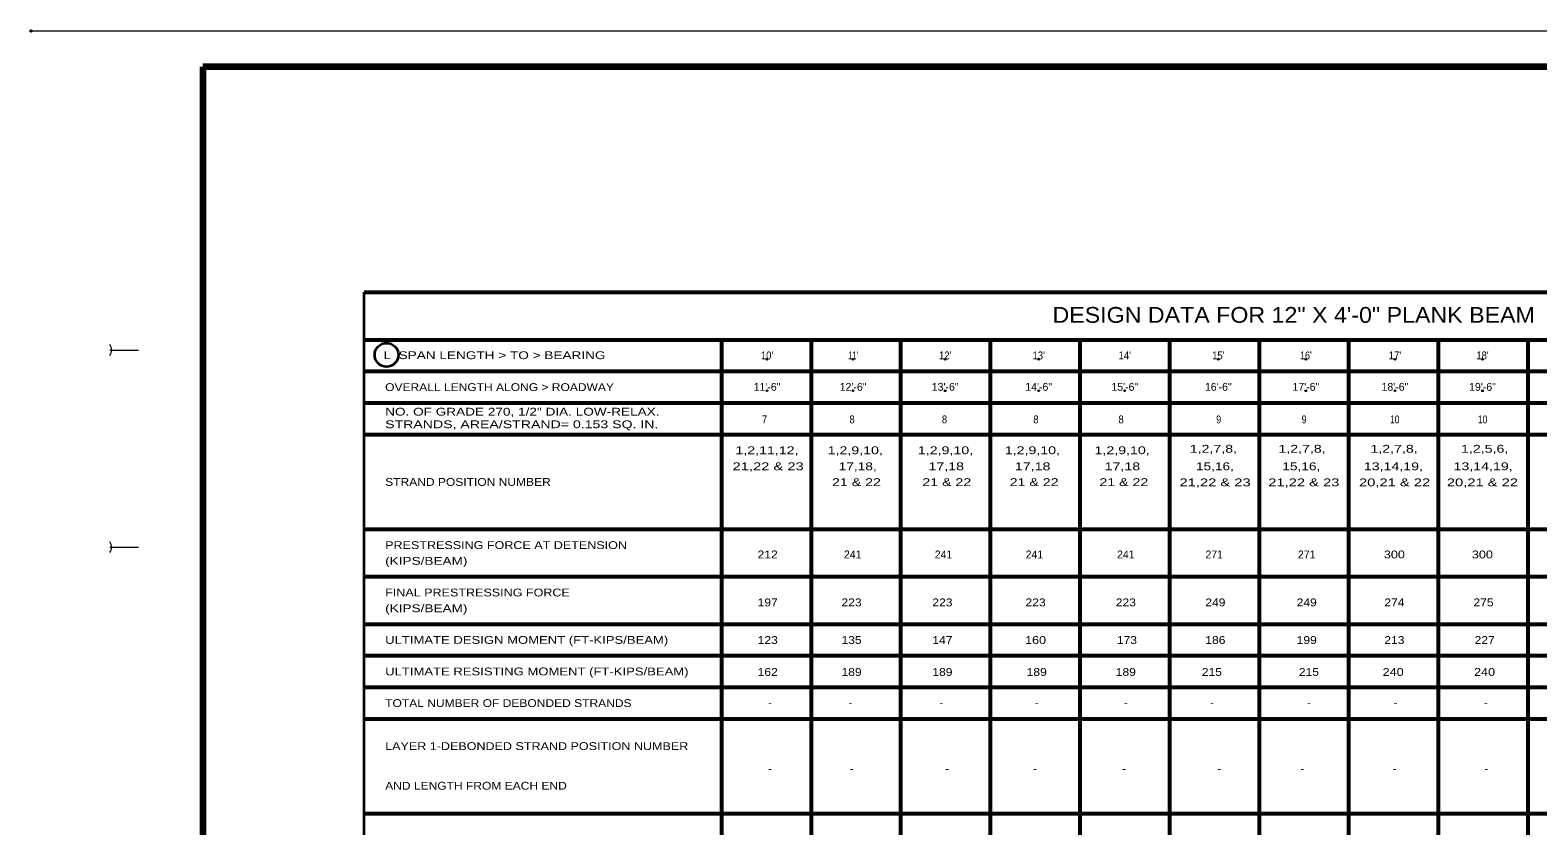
# Model space of a CAD drawing. Extents: x 758 to 1184, y 2441 to 2716.
# Drawn here: x 758.4 to 1021.3, y 2577.5 to 2716.2 of the extents above; entities that cross this region are included whole.
import ezdxf
from ezdxf.enums import TextEntityAlignment as Align

# ---------------------------------------------------------------- set-up
doc = ezdxf.new("R2010")
doc.units = 0
doc.header["$LTSCALE"] = 0.55
doc.header["$PDMODE"] = 32
doc.header["$PDSIZE"] = 0.275
for name, color, linetype, lineweight in [('1', 7, 'Continuous', 25), ('20', 7, 'Continuous', 13), ('61', 7, 'Continuous', 13), ('7', 7, 'Continuous', 53)]:
    doc.layers.add(name, color=color, linetype=linetype, lineweight=lineweight)

msp = doc.modelspace()

# ---------------------------------------------------------------- linework, layer by layer
at = {"layer": '1'}
msp.add_point((758.5283, 2716.0547), dxfattribs=at)
at = {"layer": '20'}
msp.add_lwpolyline([(879.0006, 2662.2371), (879.0006, 2662.2371), (933.7992, 2662.2371), (933.7992, 2662.2371)], close=True, dxfattribs=at)
for p in [(886.8967, 2658.8122), (901.9042, 2658.8122), (917.9579, 2658.8122), (934.2732, 2658.8122), (965.5959, 2658.8122), (980.8649, 2658.8122), (996.3955, 2658.8122), (1011.6646, 2658.8122), (886.8967, 2653.3323), (901.9042, 2653.3323), (917.9579, 2653.3323), (934.2737, 2653.3323), (949.2807, 2653.3323), (980.8649, 2653.3323), (996.3955, 2653.3323), (1011.6646, 2653.3322)]:
    msp.add_point(p, dxfattribs=at)
at = {"layer": '61'}
for p, q in [((758.5283, 2716.0547), (1183.5658, 2716.0547)), ((772.2783, 2660.4297), (777.2783, 2660.4297)), ((772.2783, 2626.0547), (777.2783, 2626.0547))]:
    msp.add_line(p, q, dxfattribs=at)
at = {"layer": '61', "lineweight": 158}
for p, q in [((788.5283, 2709.8172), (788.5283, 2447.3172)), ((1177.2783, 2709.8172), (788.5283, 2709.8172))]:
    msp.add_line(p, q, dxfattribs=at)
at = {"layer": '61'}
for centre, end in [((771.0293, 2660.4345), 36.86989), ((771.0293, 2626.0595), 36.50143)]:
    msp.add_arc(centre, 1.5625, 323.13009, end, dxfattribs=at)
at = {"layer": '7', "lineweight": 35}
for p, q in [((816.6381, 2631.3871), (816.6381, 2670.4996)), ((816.6381, 2579.6246), (816.6381, 2631.3871)), ((816.6381, 2562.5871), (816.6381, 2581.3621))]:
    msp.add_line(p, q, dxfattribs=at)
at = {"layer": '7'}
for p, q in [((816.6381, 2670.4996), (1144.6256, 2670.4996)), ((816.6381, 2662.2371), (1144.6256, 2662.2371)), ((879.0006, 2510.7871), (879.0006, 2662.2371)), ((894.6256, 2510.7871), (894.6256, 2662.2371)), ((910.2506, 2510.7871), (910.2506, 2662.2371)), ((925.8756, 2510.7871), (925.8756, 2662.2371)), ((941.5006, 2510.7871), (941.5006, 2662.2371)), ((957.1256, 2510.7871), (957.1256, 2662.2371)), ((972.7506, 2510.7871), (972.7506, 2662.2371)), ((988.3756, 2510.7871), (988.3756, 2662.2371)), ((1004.0006, 2510.7871), (1004.0006, 2662.2371)), ((1019.6256, 2510.7871), (1019.6256, 2662.2371)), ((816.6381, 2656.7246), (1144.6256, 2656.7246)), ((816.6381, 2651.2246), (1144.6256, 2651.2246)), ((816.6381, 2645.7121), (1144.6256, 2645.7121)), ((816.6381, 2629.1871), (1144.6256, 2629.1871)), ((816.6381, 2620.9371), (1144.6256, 2620.9371)), ((816.6381, 2612.6746), (1144.6256, 2612.6746)), ((816.6381, 2607.1621), (1144.6256, 2607.1621)), ((816.6381, 2601.6496), (1144.6256, 2601.6496)), ((816.6381, 2596.1496), (1144.6256, 2596.1496)), ((816.6381, 2579.6246), (1144.6256, 2579.6246))]:
    msp.add_line(p, q, dxfattribs=at)
at = {"layer": '7', "lineweight": 35}
msp.add_circle((820.5437, 2659.5955), 2.0652, dxfattribs=at)

# ---------------------------------------------------------------- texts
at = {"layer": '20'}
for s, width, p in [("10'", 0.9, (886.8968, 2658.8122)), ("11'", 0.65, (901.9043, 2658.8122)), ("12'", 0.9, (917.958, 2658.8122)), ("13'", 0.9, (934.2733, 2658.8122)), ("14'", 0.9, (949.2807, 2658.8122)), ("15'", 0.9, (965.596, 2658.8122)), ("16'", 0.85, (980.865, 2658.8122)), ("17'", 0.9, (996.3956, 2658.8122)), ("18'", 0.9, (1011.6648, 2658.8122)), ('7', 0.9, (886.45, 2647.6553)), ('8', 0.9, (901.7315, 2647.6553)), ('8', 0.9, (917.8443, 2647.6553)), ('8', 0.9, (933.7885, 2647.6553)), ('8', 0.9, (948.6401, 2647.6553)), ('9', 0.85, (965.6592, 2647.6553)), ('9', 0.85, (980.5574, 2647.6553)), ('10', 0.8, (996.3618, 2647.6553)), ('10', 0.8, (1011.69, 2647.6553)), ('1,2,11,12,', 1.35, (886.8799, 2642.2767)), ('1,2,9,10,', 1.35, (902.2795, 2642.2767)), ('1,2,9,10,', 1.35, (918.0243, 2642.2767)), ('1,2,9,10,', 1.35, (933.1757, 2642.2767)), ('1,2,9,10,', 1.35, (948.8212, 2642.2767)), ('1,2,7,8,', 1.35, (964.7364, 2642.5385)), ('1,2,7,8,', 1.35, (980.1918, 2642.5385)), ('1,2,7,8,', 1.35, (996.2395, 2642.5385)), ('1,2,5,6,', 1.35, (1012.0449, 2642.5385)), ('21,22 & 23', 1.4, (887.0949, 2639.4799)), ('17,18,', 1.3, (902.7094, 2639.4799)), ('17,18', 1.35, (918.1514, 2639.4799)), ('17,18', 1.35, (933.2205, 2639.4799)), ('17,18', 1.35, (948.866, 2639.4799)), ('15,16,', 1.3, (965.0025, 2639.4799)), ('15,16,', 1.3, (980.0716, 2639.4799)), ('13,14,19,', 1.35, (996.1288, 2639.4799)), ('13,14,19,', 1.35, (1011.7743, 2639.4799)), ('21 & 22', 1.35, (902.4945, 2636.7211)), ('21 & 22', 1.35, (918.2393, 2636.7211)), ('21 & 22', 1.35, (933.4732, 2636.7211)), ('21 & 22', 1.35, (949.1187, 2636.7211)), ('21,22 & 23', 1.4, (965.0299, 2636.6829)), ('21,22 & 23', 1.4, (980.5107, 2636.6829)), ('20,21 & 22', 1.4, (996.338, 2636.6829)), ('20,21 & 22', 1.4, (1011.6541, 2636.6829)), ('212', 1.15, (887.0103, 2624.1177)), ('300', 1.2, (996.2995, 2624.1177)), ('300', 1.2, (1011.6468, 2624.1177)), ('197', 1.15, (887.0103, 2615.7627)), ('223', 1.15, (901.6358, 2615.7627)), ('223', 1.15, (917.4776, 2615.7627)), ('223', 1.15, (933.7277, 2615.7627)), ('223', 1.15, (949.4622, 2615.7627)), ('249', 1.15, (965.0817, 2615.7627)), ('249', 1.15, (981.015, 2615.7627)), ('274', 1.15, (996.2997, 2615.7627)), ('275', 1.15, (1011.8457, 2615.7627)), ('123', 1.15, (887.0102, 2609.1983)), ('135', 1.15, (901.6358, 2609.1983)), ('147', 1.15, (917.4776, 2609.1983)), ('160', 1.2, (933.7276, 2609.1983)), ('173', 1.15, (949.661, 2609.1983)), ('186', 1.15, (965.0816, 2609.1983)), ('199', 1.15, (981.0149, 2609.1983)), ('213', 1.15, (996.2997, 2609.1983)), ('227', 1.15, (1012.0445, 2609.1983)), ('162', 1.15, (887.0102, 2603.6283)), ('189', 1.15, (901.6358, 2603.6283)), ('189', 1.15, (917.4776, 2603.6283)), ('189', 1.15, (933.9265, 2603.6283)), ('189', 1.15, (949.4622, 2603.6283)), ('215', 1.15, (964.4698, 2603.6283)), ('215', 1.15, (981.3969, 2603.6283)), ('240', 1.2, (996.0851, 2603.6283)), ('240', 1.2, (1012.0289, 2603.6283)), ('-', 1.1, (887.4079, 2598.2574)), ('-', 1.1, (901.4372, 2598.2574)), ('-', 1.1, (917.279, 2598.2574)), ('-', 1.1, (933.9265, 2598.2574)), ('-', 1.1, (949.4623, 2598.2574)), ('-', 1.1, (964.4855, 2598.2574)), ('-', 1.1, (981.4125, 2598.2574)), ('-', 1.1, (996.4984, 2598.2574)), ('-', 1.1, (1012.2433, 2598.2574)), ('-', 1.1, (887.405, 2586.7833)), ('-', 1.1, (901.6492, 2586.7833)), ('-', 1.1, (918.2986, 2586.7833)), ('-', 1.1, (933.6357, 2586.7833)), ('-', 1.1, (949.1744, 2586.7833)), ('-', 1.1, (965.7846, 2586.7833)), ('-', 1.1, (980.2412, 2586.7833)), ('-', 1.1, (996.337, 2586.7833)), ('-', 1.1, (1012.324, 2586.7833))]:
    msp.add_text(s, height=1.37, dxfattribs=dict(at, width=width)).set_placement(p, align=Align.CENTER)
for s, p in [('11\'-6"', (886.8969, 2653.3323)), ('12\'-6"', (901.9042, 2653.3323)), ('13\'-6"', (917.958, 2653.3323)), ('14\'-6"', (934.2735, 2653.3323)), ('15\'-6"', (949.2808, 2653.3323)), ('16\'-6"', (965.5962, 2653.3323)), ('17\'-6"', (980.8651, 2653.3323)), ('18\'-6"', (996.3955, 2653.3323)), ('19\'-6"', (1011.6648, 2653.3322)), ('241', (901.8347, 2624.1177)), ('241', (917.6765, 2624.1177)), ('241', (933.5289, 2624.1177)), ('241', (949.4622, 2624.1177)), ('271', (964.8829, 2624.1177)), ('271', (981.015, 2624.1177))]:
    msp.add_text(s, height=1.37, dxfattribs=at).set_placement(p, align=Align.CENTER)
at = {"layer": '7', "width": 1.1}
msp.add_text('DESIGN DATA FOR 12" X 4\'-0" PLANK BEAM', height=2.75, dxfattribs=at).set_placement((978.7388, 2665.1871), align=Align.CENTER)
at = {"layer": '7'}
for s, width, p in [('L  SPAN LENGTH > TO > BEARING', 1.3, (820.0131, 2658.8496)), ('OVERALL LENGTH ALONG > ROADWAY', 1.15, (820.3006, 2653.2871)), ('NO. OF GRADE 270, 1/2" DIA. LOW-RELAX.', 1.3, (820.3006, 2649.0031)), ('STRANDS, AREA/STRAND= 0.153 SQ. IN. ', 1.35, (820.3006, 2646.8093)), ('STRAND POSITION NUMBER', 1.15, (820.3006, 2636.7621)), ('PRESTRESSING FORCE AT DETENSION', 1.2, (820.3006, 2625.7496)), ('(KIPS/BEAM)', 1.3, (820.3006, 2622.9996)), ('FINAL PRESTRESSING FORCE', 1.2, (820.3006, 2617.4871)), ('(KIPS/BEAM)', 1.3, (820.3006, 2614.7371)), ('ULTIMATE DESIGN MOMENT (FT-KIPS/BEAM)', 1.25, (820.3006, 2609.2246)), ('ULTIMATE RESISTING MOMENT (FT-KIPS/BEAM)', 1.25, (820.3006, 2603.7246)), ('TOTAL NUMBER OF DEBONDED STRANDS', 1.15, (820.3006, 2598.2121)), ('LAYER 1-DEBONDED STRAND POSITION NUMBER', 1.2, (820.3006, 2590.7121)), ('AND LENGTH FROM EACH END', 1.15, (820.3006, 2583.7996))]:
    msp.add_text(s, height=1.363, dxfattribs=dict(at, width=width)).set_placement(p)

doc.saveas('drawing.dxf')
